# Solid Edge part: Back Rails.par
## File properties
Username: m_hel
Author: m_hel
Template: Iso Metric Part.par
Last saved by: m_hel
Revision: 13
Application: Solid Edge
Accuracy: 0,990
Material: Chrome
Face Style: Chrome
Fill Style: Normal
Virtual Style: Normal
Grouping: Uncategorized
LibraryName: Custom Materials
Coef. of Thermal Exp: 0.0
Thermal Conductivity: 0.0
Specific Heat: 0.0
Modulus of Elasticity: 0.0
Poisson's Ratio: 0.0
Yield Stress: 0.0
Ultimate Stress: 0.0
Elongation: 0.0
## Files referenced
..\Redfisher18.asm
G:\OneDriveTemp\OneDrive\Dokumendid\TLÜ tööd\3D Modelleerimine\3d modelling\veesõiduk\Deck1.par
iduk\Deck1.par
iduk\Redfisher18.asm
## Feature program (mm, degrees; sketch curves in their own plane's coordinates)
sketch for "unnamed Protrusion 1" #1 plane through (0, 0, 0) normal (0, 0, 1) x-axis (1, 0, 0)
  circle centre (366.782, 50) radius 40
sketch for "unnamed Protrusion 1" #2 plane through (0, 0, 0) normal (0, 0, 1) x-axis (1, 0, 0)
  circle centre (476.1047, -570) radius 40
extrude "unnamed Protrusion 1" add finite 5 along +normal
swept protrusion "SweptProtrusion_1"
swept protrusion "SweptProtrusion_2"
sketch for "ExtrudedProtrusion_2" plane through (0, 0, 1000) normal (0, 0, 1) x-axis (1, 0, 0)
  line (331.782, -313.5238) -> (331.782, -780.324)
  line (331.782, -780.324) -> (401.782, -780.324)
  line (401.782, -780.324) -> (401.782, -313.5238)
  line (401.782, -313.5238) -> (331.782, -313.5238)
extrude "ExtrudedProtrusion_2" add finite 20 along -normal
swept protrusion "SweptProtrusion_3"
sketch used by "ExtrudedProtrusion_3" plane through (0, 0, 1000) normal (0, 0, 1) x-axis (1, 0, 0)
extrude "ExtrudedProtrusion_3" add finite 20 along -normal
swept protrusion "SweptProtrusion_6"
swept protrusion "SweptProtrusion_7"
mirror "unnamed Mirror 1" of "unnamed Protrusion 1", "SweptProtrusion_3", "SweptProtrusion_6", "SweptProtrusion_2", "SweptProtrusion_7", "ExtrudedProtrusion_2" about plane through (0, 0, 0) normal (1, 0, 0)
extrude "unnamed Protrusion 2" add finite 5
swept protrusion "unnamed SweptProtrusion 1"
extrude "unnamed Protrusion 3" add finite 20
swept protrusion "unnamed SweptProtrusion 2"
swept protrusion "unnamed SweptProtrusion 3"
swept protrusion "unnamed SweptProtrusion 4"
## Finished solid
Body 1: solid body, 52 faces, 110 edges, 60 vertices.
  Faces by surface: plane 28, torus 12, cylinder 8, spline 4
  Edges by curve: circle 48, intersection 46, line 16
Bounding box of the edges (mm; curved faces can reach further): 1032.209 x 925.000 x 1035.000, from (-516.1047, -835, 0) to (516.1047, 90, 1035).
Cylindrical faces by radius (mm): R35 x4, R40 x4
Toroidal faces (ring radius, tube radius in mm): R163.5238 r35 x2, R169.676 r35 x2, R500 r22.5 x8
Planar faces by outward normal: +x 3, +z 11, -x 3, -z 11
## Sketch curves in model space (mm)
arc centre (-42.1725, -575.7221, 660) radius 500 from (456.8952, -545.2039, 660) through (429.6944, -410.369, 660) to (366.782, -288.0483, 660)
arc centre (-21.3948, -432.8827, 330) radius 500 from (466.5733, -541.911, 330) through (465.3177, -318.3795, 330) to (366.782, -117.7339, 330)
line (366.782, 50, 5) -> (366.782, -463.5238, 1000)
circle centre (366.782, 50, 5) radius 25
line (366.782, 50, 1000) -> (366.782, -958.1509, 1000)
line (401.782, -780.324, 1000) -> (401.782, -313.5238, 1000)
line (401.782, -313.5238, 1000) -> (331.782, -313.5238, 1000)
line (331.782, -313.5238, 1000) -> (331.782, -780.324, 1000)
line (331.782, -780.324, 1000) -> (401.782, -780.324, 1000)
line (35, -780, 1000) -> (35, -300, 1000)
line (35, -300, 1000) -> (-35, -300, 1000)
line (-35, -300, 1000) -> (-35, -780, 1000)
line (-35, -780, 1000) -> (35, -780, 1000)
circle centre (476.1047, -570, 5) radius 25
line (446.9239, 0, 1000) -> (476.1047, 0, 5)
spline (0, -630.324, 1000) -> (0, -540.9583, 599.1314) -> (0, -570, 5)
circle centre (0, -800, 1000) radius 35
arc centre (-289.5524, -636.4762, 1000) radius 163.5238 from (-289.5524, -800, 1000) through (-408.4952, -748.6931, 1000) to (-453.0761, -636.4762, 1000)
line (-453.0761, -636.4762, 1000) -> (-453.0761, -469.676, 1000)
arc centre (-283.4001, -469.676, 1000) radius 169.676 from (-453.0761, -469.676, 1000) through (-399.8389, -346.2581, 1000) to (-283.4001, -300, 1000)
line (-283.4001, -300, 1000) -> (283.4001, -300, 1000)
arc centre (283.4001, -463.5238, 1000) radius 163.5238 from (283.4001, -300, 1000) through (402.343, -351.3069, 1000) to (446.9239, -463.5238, 1000)
line (446.9239, -463.5238, 1000) -> (446.9239, -630.324, 1000)
arc centre (277.2479, -630.324, 1000) radius 169.676 from (277.2479, -800, 1000) through (400.6657, -746.7627, 1000) to (446.9239, -630.324, 1000)
line (277.2479, -800, 1000) -> (-289.5524, -800, 1000)
circle centre (366.782, 50, 0) radius 40
circle centre (476.1047, -570, 0) radius 40
line (316.782, 0, 0) -> (426.1047, -620, 0)
line (1205, -620, 0) -> (426.1047, -620, 0)
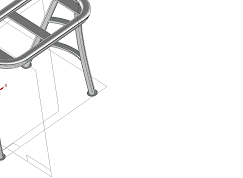
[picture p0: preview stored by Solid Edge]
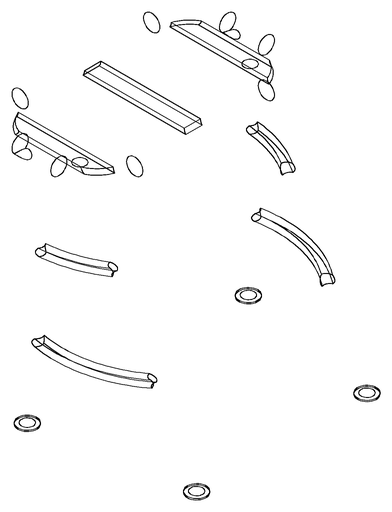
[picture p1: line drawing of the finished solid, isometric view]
